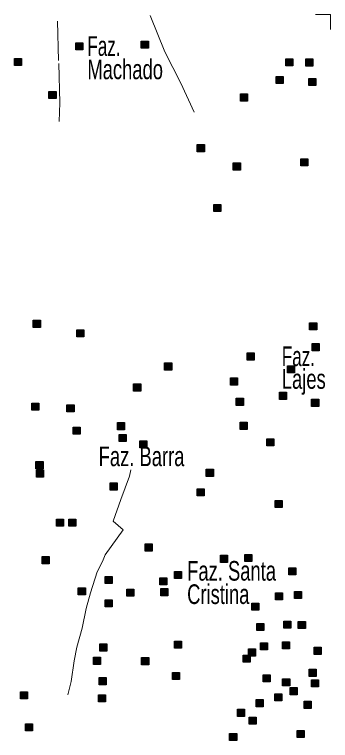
# Model space of a CAD drawing. Extents: x 445.6 to 500, y 8618.1 to 8673.4.
# Drawn here: x 497.42 to 500, y 8667.52 to 8673.43 of the extents above; entities that cross this region are included whole.
import ezdxf

# ---------------------------------------------------------------- set-up
doc = ezdxf.new("R2010")
doc.units = 0
doc.header["$LTSCALE"] = 0.064
doc.linetypes.add('DOT_DASHED', pattern=[7.7, 5, -1.2, 0.3, -1.2])
for name, color, linetype, lineweight in [('2', 7, 'Continuous', 25), ('22', 7, 'DOT_DASHED', 13), ('63', 7, 'Continuous', 13)]:
    doc.layers.add(name, color=color, linetype=linetype, lineweight=lineweight)
doc.layers.add('61', color=7, linetype='Continuous')

msp = doc.modelspace()

# ---------------------------------------------------------------- hatches: boundary and pattern name
at = {"layer": '2'}
for points in [[(498.458, 8673.2149), (498.516, 8673.2149), (498.516, 8673.1569), (498.458, 8673.1569)], [(497.9243, 8673.2013), (497.9823, 8673.2013), (497.9823, 8673.1433), (497.9243, 8673.1433)], [(497.4244, 8673.0726), (497.4824, 8673.0726), (497.4824, 8673.0146), (497.4244, 8673.0146)], [(499.6351, 8673.0703), (499.6931, 8673.0703), (499.6931, 8673.0123), (499.6351, 8673.0123)], [(499.799, 8673.0692), (499.857, 8673.0692), (499.857, 8673.0112), (499.799, 8673.0112)], [(499.5567, 8672.9267), (499.6147, 8672.9267), (499.6147, 8672.8687), (499.5567, 8672.8687)], [(499.8226, 8672.9099), (499.8806, 8672.9099), (499.8806, 8672.8519), (499.8226, 8672.8519)], [(497.7047, 8672.8049), (497.7627, 8672.8049), (497.7627, 8672.7469), (497.7047, 8672.7469)], [(499.2653, 8672.7846), (499.3233, 8672.7846), (499.3233, 8672.7266), (499.2653, 8672.7266)], [(498.914, 8672.3712), (498.972, 8672.3712), (498.972, 8672.3132), (498.914, 8672.3132)], [(499.2078, 8672.2222), (499.2658, 8672.2222), (499.2658, 8672.1642), (499.2078, 8672.1642)], [(499.7584, 8672.2561), (499.8164, 8672.2561), (499.8164, 8672.1981), (499.7584, 8672.1981)], [(499.0485, 8671.8834), (499.1065, 8671.8834), (499.1065, 8671.8254), (499.0485, 8671.8254)], [(497.5775, 8670.9405), (497.6355, 8670.9405), (497.6355, 8670.8825), (497.5775, 8670.8825)], [(499.8294, 8670.9204), (499.8874, 8670.9204), (499.8874, 8670.8624), (499.8294, 8670.8624)], [(497.9322, 8670.8626), (497.9902, 8670.8626), (497.9902, 8670.8046), (497.9322, 8670.8046)], [(499.8497, 8670.751), (499.9077, 8670.751), (499.9077, 8670.693), (499.8497, 8670.693)], [(499.3199, 8670.6741), (499.3779, 8670.6741), (499.3779, 8670.6161), (499.3199, 8670.6161)], [(498.6477, 8670.5928), (498.7057, 8670.5928), (498.7057, 8670.5348), (498.6477, 8670.5348)], [(499.6488, 8670.5697), (499.7068, 8670.5697), (499.7068, 8670.5117), (499.6488, 8670.5117)], [(499.1848, 8670.4708), (499.2428, 8670.4708), (499.2428, 8670.4128), (499.1848, 8670.4128)], [(498.3949, 8670.4221), (498.4529, 8670.4221), (498.4529, 8670.3641), (498.3949, 8670.3641)], [(499.584, 8670.3542), (499.642, 8670.3542), (499.642, 8670.2962), (499.584, 8670.2962)], [(497.5648, 8670.2663), (497.6228, 8670.2663), (497.6228, 8670.2083), (497.5648, 8670.2083)], [(499.2321, 8670.3048), (499.2901, 8670.3048), (499.2901, 8670.2468), (499.2321, 8670.2468)], [(499.8463, 8670.297), (499.9043, 8670.297), (499.9043, 8670.239), (499.8463, 8670.239)], [(497.852, 8670.2528), (497.91, 8670.2528), (497.91, 8670.1948), (497.852, 8670.1948)], [(498.2632, 8670.1071), (498.3212, 8670.1071), (498.3212, 8670.0491), (498.2632, 8670.0491)], [(499.2634, 8670.1093), (499.3214, 8670.1093), (499.3214, 8670.0513), (499.2634, 8670.0513)], [(497.9026, 8670.0698), (497.9606, 8670.0698), (497.9606, 8670.0118), (497.9026, 8670.0118)], [(498.2767, 8670.0098), (498.3347, 8670.0098), (498.3347, 8669.9518), (498.2767, 8669.9518)], [(499.4806, 8669.9746), (499.5386, 8669.9746), (499.5386, 8669.9166), (499.4806, 8669.9166)], [(498.4456, 8669.959), (498.5036, 8669.959), (498.5036, 8669.901), (498.4456, 8669.901)], [(497.599, 8669.7894), (497.657, 8669.7894), (497.657, 8669.7314), (497.599, 8669.7314)], [(498.9874, 8669.7273), (499.0454, 8669.7273), (499.0454, 8669.6693), (498.9874, 8669.6693)], [(497.604, 8669.7213), (497.662, 8669.7213), (497.662, 8669.6633), (497.604, 8669.6633)], [(498.2038, 8669.6155), (498.2618, 8669.6155), (498.2618, 8669.5575), (498.2038, 8669.5575)], [(498.9131, 8669.5681), (498.9711, 8669.5681), (498.9711, 8669.5101), (498.9131, 8669.5101)], [(499.5482, 8669.4732), (499.6062, 8669.4732), (499.6062, 8669.4152), (499.5482, 8669.4152)], [(497.7661, 8669.3209), (497.8241, 8669.3209), (497.8241, 8669.2629), (497.7661, 8669.2629)], [(497.866, 8669.3207), (497.924, 8669.3207), (497.924, 8669.2627), (497.866, 8669.2627)], [(498.4892, 8669.119), (498.5472, 8669.119), (498.5472, 8669.061), (498.4892, 8669.061)], [(499.103, 8669.0267), (499.161, 8669.0267), (499.161, 8668.9687), (499.103, 8668.9687)], [(499.3016, 8669.0328), (499.3596, 8669.0328), (499.3596, 8668.9748), (499.3016, 8668.9748)], [(497.6498, 8669.0158), (497.7078, 8669.0158), (497.7078, 8668.9578), (497.6498, 8668.9578)], [(499.6596, 8668.9243), (499.7176, 8668.9243), (499.7176, 8668.8663), (499.6596, 8668.8663)], [(498.1633, 8668.8532), (498.2213, 8668.8532), (498.2213, 8668.7952), (498.1633, 8668.7952)], [(498.6091, 8668.843), (498.6671, 8668.843), (498.6671, 8668.785), (498.6091, 8668.785)], [(498.7274, 8668.8939), (498.7854, 8668.8939), (498.7854, 8668.8359), (498.7274, 8668.8359)], [(497.9437, 8668.7617), (498.0017, 8668.7617), (498.0017, 8668.7037), (497.9437, 8668.7037)], [(498.3389, 8668.7516), (498.3969, 8668.7516), (498.3969, 8668.6936), (498.3389, 8668.6936)], [(498.6159, 8668.7549), (498.6739, 8668.7549), (498.6739, 8668.6969), (498.6159, 8668.6969)], [(499.5515, 8668.7211), (499.6095, 8668.7211), (499.6095, 8668.6631), (499.5515, 8668.6631)], [(499.7069, 8668.7312), (499.7649, 8668.7312), (499.7649, 8668.6732), (499.7069, 8668.6732)], [(498.1633, 8668.6635), (498.2213, 8668.6635), (498.2213, 8668.6055), (498.1633, 8668.6055)], [(499.359, 8668.6364), (499.417, 8668.6364), (499.417, 8668.5784), (499.359, 8668.5784)], [(499.6191, 8668.4907), (499.6771, 8668.4907), (499.6771, 8668.4327), (499.6191, 8668.4327)], [(499.7373, 8668.4873), (499.7953, 8668.4873), (499.7953, 8668.4293), (499.7373, 8668.4293)], [(499.3995, 8668.4704), (499.4575, 8668.4704), (499.4575, 8668.4124), (499.3995, 8668.4124)], [(498.7274, 8668.3281), (498.7854, 8668.3281), (498.7854, 8668.2701), (498.7274, 8668.2701)], [(499.4299, 8668.3145), (499.4879, 8668.3145), (499.4879, 8668.2565), (499.4299, 8668.2565)], [(499.609, 8668.3213), (499.667, 8668.3213), (499.667, 8668.2633), (499.609, 8668.2633)], [(498.1193, 8668.3043), (498.1773, 8668.3043), (498.1773, 8668.2463), (498.1193, 8668.2463)], [(499.332, 8668.2637), (499.39, 8668.2637), (499.39, 8668.2057), (499.332, 8668.2057)], [(499.8657, 8668.2772), (499.9237, 8668.2772), (499.9237, 8668.2192), (499.8657, 8668.2192)], [(498.0675, 8668.1958), (498.1255, 8668.1958), (498.1255, 8668.1378), (498.0675, 8668.1378)], [(498.4605, 8668.1925), (498.5185, 8668.1925), (498.5185, 8668.1345), (498.4605, 8668.1345)], [(499.2881, 8668.2129), (499.3461, 8668.2129), (499.3461, 8668.1549), (499.2881, 8668.1549)], [(498.7119, 8668.0713), (498.7699, 8668.0713), (498.7699, 8668.0133), (498.7119, 8668.0133)], [(499.825, 8668.0976), (499.883, 8668.0976), (499.883, 8668.0396), (499.825, 8668.0396)], [(498.1148, 8668.0298), (498.1728, 8668.0298), (498.1728, 8667.9718), (498.1148, 8667.9718)], [(499.4511, 8668.0536), (499.5091, 8668.0536), (499.5091, 8667.9956), (499.4511, 8667.9956)], [(499.6099, 8668.0197), (499.6679, 8668.0197), (499.6679, 8667.9617), (499.6099, 8667.9617)], [(499.8453, 8668.0129), (499.9033, 8668.0129), (499.9033, 8667.9549), (499.8453, 8667.9549)], [(497.473, 8667.9146), (497.531, 8667.9146), (497.531, 8667.8566), (497.473, 8667.8566)], [(499.5457, 8667.8977), (499.6037, 8667.8977), (499.6037, 8667.8397), (499.5457, 8667.8397)], [(499.6707, 8667.9485), (499.7287, 8667.9485), (499.7287, 8667.8905), (499.6707, 8667.8905)], [(498.108, 8667.8909), (498.166, 8667.8909), (498.166, 8667.8329), (498.108, 8667.8329)], [(499.3937, 8667.8503), (499.4517, 8667.8503), (499.4517, 8667.7923), (499.3937, 8667.7923)], [(499.7845, 8667.8367), (499.8425, 8667.8367), (499.8425, 8667.7787), (499.7845, 8667.7787)], [(499.2417, 8667.7724), (499.2997, 8667.7724), (499.2997, 8667.7144), (499.2417, 8667.7144)], [(499.3363, 8667.708), (499.3943, 8667.708), (499.3943, 8667.65), (499.3363, 8667.65)], [(497.5136, 8667.6541), (497.5716, 8667.6541), (497.5716, 8667.5961), (497.5136, 8667.5961)], [(499.7281, 8667.5996), (499.7861, 8667.5996), (499.7861, 8667.5416), (499.7281, 8667.5416)], [(499.1775, 8667.5758), (499.2355, 8667.5758), (499.2355, 8667.5178), (499.1775, 8667.5178)]]:
    msp.add_hatch(color=256, dxfattribs=at).paths.add_polyline_path(points)

# ---------------------------------------------------------------- linework, layer by layer
for points in [[(498.458, 8673.2149), (498.516, 8673.2149), (498.516, 8673.1569), (498.458, 8673.1569)], [(497.9243, 8673.2013), (497.9823, 8673.2013), (497.9823, 8673.1433), (497.9243, 8673.1433)], [(497.4244, 8673.0726), (497.4824, 8673.0726), (497.4824, 8673.0146), (497.4244, 8673.0146)], [(499.6351, 8673.0703), (499.6931, 8673.0703), (499.6931, 8673.0123), (499.6351, 8673.0123)], [(499.799, 8673.0692), (499.857, 8673.0692), (499.857, 8673.0112), (499.799, 8673.0112)], [(499.5567, 8672.9267), (499.6147, 8672.9267), (499.6147, 8672.8687), (499.5567, 8672.8687)], [(499.8226, 8672.9099), (499.8806, 8672.9099), (499.8806, 8672.8519), (499.8226, 8672.8519)], [(497.7047, 8672.8049), (497.7627, 8672.8049), (497.7627, 8672.7469), (497.7047, 8672.7469)], [(499.2653, 8672.7846), (499.3233, 8672.7846), (499.3233, 8672.7266), (499.2653, 8672.7266)], [(498.914, 8672.3712), (498.972, 8672.3712), (498.972, 8672.3132), (498.914, 8672.3132)], [(499.2078, 8672.2222), (499.2658, 8672.2222), (499.2658, 8672.1642), (499.2078, 8672.1642)], [(499.7584, 8672.2561), (499.8164, 8672.2561), (499.8164, 8672.1981), (499.7584, 8672.1981)], [(499.0485, 8671.8834), (499.1065, 8671.8834), (499.1065, 8671.8254), (499.0485, 8671.8254)], [(497.5775, 8670.9405), (497.6355, 8670.9405), (497.6355, 8670.8825), (497.5775, 8670.8825)], [(499.8294, 8670.9204), (499.8874, 8670.9204), (499.8874, 8670.8624), (499.8294, 8670.8624)], [(497.9322, 8670.8626), (497.9902, 8670.8626), (497.9902, 8670.8046), (497.9322, 8670.8046)], [(499.8497, 8670.751), (499.9077, 8670.751), (499.9077, 8670.693), (499.8497, 8670.693)], [(499.3199, 8670.6741), (499.3779, 8670.6741), (499.3779, 8670.6161), (499.3199, 8670.6161)], [(498.6477, 8670.5928), (498.7057, 8670.5928), (498.7057, 8670.5348), (498.6477, 8670.5348)], [(499.6488, 8670.5697), (499.7068, 8670.5697), (499.7068, 8670.5117), (499.6488, 8670.5117)], [(499.1848, 8670.4708), (499.2428, 8670.4708), (499.2428, 8670.4128), (499.1848, 8670.4128)], [(498.3949, 8670.4221), (498.4529, 8670.4221), (498.4529, 8670.3641), (498.3949, 8670.3641)], [(499.584, 8670.3542), (499.642, 8670.3542), (499.642, 8670.2962), (499.584, 8670.2962)], [(497.5648, 8670.2663), (497.6228, 8670.2663), (497.6228, 8670.2083), (497.5648, 8670.2083)], [(499.2321, 8670.3048), (499.2901, 8670.3048), (499.2901, 8670.2468), (499.2321, 8670.2468)], [(499.8463, 8670.297), (499.9043, 8670.297), (499.9043, 8670.239), (499.8463, 8670.239)], [(497.852, 8670.2528), (497.91, 8670.2528), (497.91, 8670.1948), (497.852, 8670.1948)], [(498.2632, 8670.1071), (498.3212, 8670.1071), (498.3212, 8670.0491), (498.2632, 8670.0491)], [(499.2634, 8670.1093), (499.3214, 8670.1093), (499.3214, 8670.0513), (499.2634, 8670.0513)], [(497.9026, 8670.0698), (497.9606, 8670.0698), (497.9606, 8670.0118), (497.9026, 8670.0118)], [(498.2767, 8670.0098), (498.3347, 8670.0098), (498.3347, 8669.9518), (498.2767, 8669.9518)], [(499.4806, 8669.9746), (499.5386, 8669.9746), (499.5386, 8669.9166), (499.4806, 8669.9166)], [(498.4456, 8669.959), (498.5036, 8669.959), (498.5036, 8669.901), (498.4456, 8669.901)], [(497.599, 8669.7894), (497.657, 8669.7894), (497.657, 8669.7314), (497.599, 8669.7314)], [(498.9874, 8669.7273), (499.0454, 8669.7273), (499.0454, 8669.6693), (498.9874, 8669.6693)], [(497.604, 8669.7213), (497.662, 8669.7213), (497.662, 8669.6633), (497.604, 8669.6633)], [(498.2038, 8669.6155), (498.2618, 8669.6155), (498.2618, 8669.5575), (498.2038, 8669.5575)], [(498.9131, 8669.5681), (498.9711, 8669.5681), (498.9711, 8669.5101), (498.9131, 8669.5101)], [(499.5482, 8669.4732), (499.6062, 8669.4732), (499.6062, 8669.4152), (499.5482, 8669.4152)], [(497.7661, 8669.3209), (497.8241, 8669.3209), (497.8241, 8669.2629), (497.7661, 8669.2629)], [(497.866, 8669.3207), (497.924, 8669.3207), (497.924, 8669.2627), (497.866, 8669.2627)], [(498.4892, 8669.119), (498.5472, 8669.119), (498.5472, 8669.061), (498.4892, 8669.061)], [(499.103, 8669.0267), (499.161, 8669.0267), (499.161, 8668.9687), (499.103, 8668.9687)], [(499.3016, 8669.0328), (499.3596, 8669.0328), (499.3596, 8668.9748), (499.3016, 8668.9748)], [(497.6498, 8669.0158), (497.7078, 8669.0158), (497.7078, 8668.9578), (497.6498, 8668.9578)], [(499.6596, 8668.9243), (499.7176, 8668.9243), (499.7176, 8668.8663), (499.6596, 8668.8663)], [(498.1633, 8668.8532), (498.2213, 8668.8532), (498.2213, 8668.7952), (498.1633, 8668.7952)], [(498.6091, 8668.843), (498.6671, 8668.843), (498.6671, 8668.785), (498.6091, 8668.785)], [(498.7274, 8668.8939), (498.7854, 8668.8939), (498.7854, 8668.8359), (498.7274, 8668.8359)], [(497.9437, 8668.7617), (498.0017, 8668.7617), (498.0017, 8668.7037), (497.9437, 8668.7037)], [(498.3389, 8668.7516), (498.3969, 8668.7516), (498.3969, 8668.6936), (498.3389, 8668.6936)], [(498.6159, 8668.7549), (498.6739, 8668.7549), (498.6739, 8668.6969), (498.6159, 8668.6969)], [(499.5515, 8668.7211), (499.6095, 8668.7211), (499.6095, 8668.6631), (499.5515, 8668.6631)], [(499.7069, 8668.7312), (499.7649, 8668.7312), (499.7649, 8668.6732), (499.7069, 8668.6732)], [(498.1633, 8668.6635), (498.2213, 8668.6635), (498.2213, 8668.6055), (498.1633, 8668.6055)], [(499.359, 8668.6364), (499.417, 8668.6364), (499.417, 8668.5784), (499.359, 8668.5784)], [(499.6191, 8668.4907), (499.6771, 8668.4907), (499.6771, 8668.4327), (499.6191, 8668.4327)], [(499.7373, 8668.4873), (499.7953, 8668.4873), (499.7953, 8668.4293), (499.7373, 8668.4293)], [(499.3995, 8668.4704), (499.4575, 8668.4704), (499.4575, 8668.4124), (499.3995, 8668.4124)], [(498.7274, 8668.3281), (498.7854, 8668.3281), (498.7854, 8668.2701), (498.7274, 8668.2701)], [(499.4299, 8668.3145), (499.4879, 8668.3145), (499.4879, 8668.2565), (499.4299, 8668.2565)], [(499.609, 8668.3213), (499.667, 8668.3213), (499.667, 8668.2633), (499.609, 8668.2633)], [(498.1193, 8668.3043), (498.1773, 8668.3043), (498.1773, 8668.2463), (498.1193, 8668.2463)], [(499.332, 8668.2637), (499.39, 8668.2637), (499.39, 8668.2057), (499.332, 8668.2057)], [(499.8657, 8668.2772), (499.9237, 8668.2772), (499.9237, 8668.2192), (499.8657, 8668.2192)], [(498.0675, 8668.1958), (498.1255, 8668.1958), (498.1255, 8668.1378), (498.0675, 8668.1378)], [(498.4605, 8668.1925), (498.5185, 8668.1925), (498.5185, 8668.1345), (498.4605, 8668.1345)], [(499.2881, 8668.2129), (499.3461, 8668.2129), (499.3461, 8668.1549), (499.2881, 8668.1549)], [(498.7119, 8668.0713), (498.7699, 8668.0713), (498.7699, 8668.0133), (498.7119, 8668.0133)], [(499.825, 8668.0976), (499.883, 8668.0976), (499.883, 8668.0396), (499.825, 8668.0396)], [(498.1148, 8668.0298), (498.1728, 8668.0298), (498.1728, 8667.9718), (498.1148, 8667.9718)], [(499.4511, 8668.0536), (499.5091, 8668.0536), (499.5091, 8667.9956), (499.4511, 8667.9956)], [(499.6099, 8668.0197), (499.6679, 8668.0197), (499.6679, 8667.9617), (499.6099, 8667.9617)], [(499.8453, 8668.0129), (499.9033, 8668.0129), (499.9033, 8667.9549), (499.8453, 8667.9549)], [(497.473, 8667.9146), (497.531, 8667.9146), (497.531, 8667.8566), (497.473, 8667.8566)], [(499.5457, 8667.8977), (499.6037, 8667.8977), (499.6037, 8667.8397), (499.5457, 8667.8397)], [(499.6707, 8667.9485), (499.7287, 8667.9485), (499.7287, 8667.8905), (499.6707, 8667.8905)], [(498.108, 8667.8909), (498.166, 8667.8909), (498.166, 8667.8329), (498.108, 8667.8329)], [(499.3937, 8667.8503), (499.4517, 8667.8503), (499.4517, 8667.7923), (499.3937, 8667.7923)], [(499.7845, 8667.8367), (499.8425, 8667.8367), (499.8425, 8667.7787), (499.7845, 8667.7787)], [(499.2417, 8667.7724), (499.2997, 8667.7724), (499.2997, 8667.7144), (499.2417, 8667.7144)], [(499.3363, 8667.708), (499.3943, 8667.708), (499.3943, 8667.65), (499.3363, 8667.65)], [(497.5136, 8667.6541), (497.5716, 8667.6541), (497.5716, 8667.5961), (497.5136, 8667.5961)], [(499.7281, 8667.5996), (499.7861, 8667.5996), (499.7861, 8667.5416), (499.7281, 8667.5416)], [(499.1775, 8667.5758), (499.2355, 8667.5758), (499.2355, 8667.5178), (499.1775, 8667.5178)]]:
    msp.add_lwpolyline(points, close=True, dxfattribs=at)
at = {"layer": '22'}
for points in [[(497.7889, 8672.5594), (497.7927, 8672.7119), (497.7839, 8673.0559), (497.7747, 8673.431)], [(498.8885, 8672.6354), (498.7795, 8672.8708), (498.65, 8673.1266), (498.5284, 8673.4311)], [(498.3725, 8669.7214), (498.3626, 8669.6696), (498.2909, 8669.4806), (498.2289, 8669.3046), (498.3104, 8669.2329), (498.1634, 8669.0305), (498.1406, 8668.9768)], [(498.1406, 8668.9768), (498.0978, 8668.8902), (498.0425, 8668.7192), (498.0073, 8668.5934), (497.9772, 8668.4325), (497.9319, 8668.2766), (497.9118, 8668.1659), (497.8851, 8667.9976), (497.8601, 8667.8904)]]:
    msp.add_lwpolyline(points, dxfattribs=at)
at = {"layer": '63'}
msp.add_lwpolyline([(500, 8673.3079), (500, 8673.4311), (499.8786, 8673.4311)], dxfattribs=at)

# ---------------------------------------------------------------- texts
at = {"layer": '61'}
for s, width, p in [('Faz.', 0.65, (498.0185, 8673.0944)), ('Machado', 0.7, (498.0185, 8672.9044)), ('Faz.', 0.65, (499.6033, 8670.5674)), ('Lajes', 0.7, (499.6033, 8670.3824)), ('Faz. Barra', 0.7, (498.1103, 8669.7524)), ('Faz. Santa', 0.7, (498.8317, 8668.8196)), ('Cristina', 0.7, (498.8317, 8668.6296))]:
    msp.add_text(s, height=0.16, dxfattribs=dict(at, width=width)).set_placement(p)

doc.saveas('drawing.dxf')
